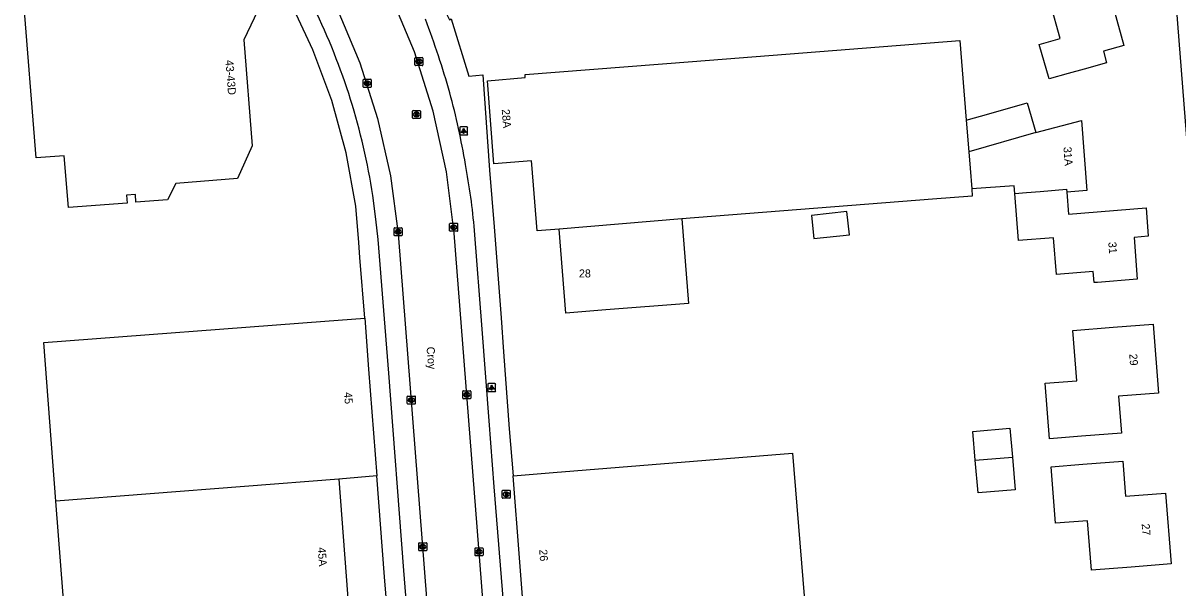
# Model space of a CAD drawing. Extents: x 157793 to 159380, y 380882 to 382313.
# Drawn here: x 158058.2 to 158202.5, y 381350.9 to 381421.5 of the extents above; entities that cross this region are included whole.
import ezdxf

# ---------------------------------------------------------------- set-up
doc = ezdxf.new("R2010")
doc.units = 0
for name, color, linetype in [('IMGEO_Brandkraan', 7, 'Continuous'), ('IMGEO_Kolk', 7, 'Continuous'), ('IMGEO_Lichtpunt', 7, 'Continuous'), ('IMGEO_Openbare_ruimte_label', 7, 'Continuous'), ('IMGEO_Pand', 7, 'Continuous'), ('IMGEO_Pand_nummerreeks', 7, 'Continuous'), ('IMGEO_Rijbaan_lokaal_gesloten', 7, 'Continuous'), ('IMGEO_Rioolput', 7, 'Continuous'), ('IMGEO_Voetpad_open', 7, 'Continuous')]:
    doc.layers.add(name, color=color, linetype=linetype)

msp = doc.modelspace()

# ---------------------------------------------------------------- linework, layer by layer
at = {"layer": 'IMGEO_Brandkraan'}
for p, q in [((158118.1, 381362.21), (158118.1, 381363.06)), ((158118.18, 381363.13), (158119.03, 381363.13)), ((158118.59, 381362.91), (158118.61, 381362.91)), ((158119.1, 381363.06), (158119.1, 381362.21)), ((158119.03, 381362.13), (158118.18, 381362.13)), ((158118.61, 381362.35), (158118.59, 381362.35))]:
    msp.add_line(p, q, dxfattribs=at)
for points in [[(158118.1, 381362.21), (158118.1, 381363.06)], [(158118.18, 381363.13), (158119.03, 381363.13)], [(158118.45, 381362.83), (158118.45, 381362.43), (158118.66, 381362.43)], [(158118.68, 381362.83), (158118.45, 381362.83)], [(158118.63, 381362.75), (158118.57, 381362.75), (158118.57, 381362.68)], [(158118.57, 381362.68), (158118.63, 381362.68)], [(158118.64, 381362.6), (158118.57, 381362.6), (158118.57, 381362.52)], [(158118.57, 381362.52), (158118.64, 381362.52)], [(158119.1, 381363.06), (158119.1, 381362.21)], [(158119.03, 381362.13), (158118.18, 381362.13)]]:
    msp.add_lwpolyline(points, dxfattribs=at)
for centre, radius, start, end in [((158118.18, 381363.06), 0.0765, 91.552, 178.448), ((158118.18, 381363.06), 0.0765, 91.552, 178.448), ((158118.63, 381362.71), 0.0379, 267.8285, 90.9355), ((158118.64, 381362.56), 0.0404, 269.8759, 90.5077), ((158118.67, 381362.68), 0.251, 268.6676, 293.5347), ((158118.68, 381362.69), 0.145, 59.4692, 91.5367), ((158118.71, 381362.73), 0.0922, 285.5137, 58.1501), ((158118.71, 381362.54), 0.105, 301.3115, 78.989), ((158119.03, 381363.06), 0.0765, 1.552, 88.448), ((158119.03, 381363.06), 0.0765, 1.552, 88.448), ((158118.18, 381362.21), 0.0765, 181.552, 268.448), ((158118.18, 381362.21), 0.0765, 181.552, 268.448), ((158119.03, 381362.21), 0.0765, 271.552, 358.448), ((158119.03, 381362.21), 0.0765, 271.552, 358.448)]:
    msp.add_arc(centre, radius, start, end, dxfattribs=at)
for centre, major_axis, ratio, start_param, end_param in [((158118.59, 381362.63), (-0.387, 0.002), 0.722429, 4.712389, 7.853982), ((158118.61, 381362.63), (-0.39, 0.002), 0.717154, 1.570796, 4.712389)]:
    msp.add_ellipse(centre, major_axis=major_axis, ratio=ratio, start_param=start_param, end_param=end_param, dxfattribs=at)
at = {"layer": 'IMGEO_Kolk'}
for p, q in [((158107.19, 381416.27), (158107.19, 381417.12)), ((158107.26, 381417.19), (158108.12, 381417.19)), ((158108.12, 381416.19), (158107.26, 381416.19)), ((158107.7, 381416.41), (158107.67, 381416.41)), ((158107.68, 381416.97), (158107.7, 381416.97)), ((158108.19, 381417.12), (158108.19, 381416.27)), ((158100.73, 381413.55), (158100.73, 381414.4)), ((158100.8, 381414.47), (158101.66, 381414.47)), ((158101.73, 381414.4), (158101.73, 381413.55)), ((158101.66, 381413.47), (158100.8, 381413.47)), ((158101.24, 381413.69), (158101.21, 381413.69)), ((158101.22, 381414.25), (158101.24, 381414.25)), ((158104.59, 381394.99), (158104.59, 381395.85)), ((158104.66, 381395.92), (158105.52, 381395.92)), ((158105.08, 381395.7), (158105.1, 381395.7)), ((158105.59, 381395.85), (158105.59, 381394.99)), ((158111.53, 381395.55), (158111.53, 381396.41)), ((158111.61, 381396.48), (158112.46, 381396.48)), ((158112.02, 381396.26), (158112.04, 381396.26)), ((158112.04, 381395.7), (158112.02, 381395.7)), ((158112.53, 381396.41), (158112.53, 381395.55)), ((158105.52, 381394.92), (158104.66, 381394.92)), ((158105.1, 381395.14), (158105.07, 381395.14)), ((158112.46, 381395.48), (158111.61, 381395.48)), ((158113.17, 381374.63), (158113.17, 381375.48)), ((158113.24, 381375.56), (158114.1, 381375.56)), ((158114.17, 381375.48), (158114.17, 381374.63)), ((158106.24, 381373.97), (158106.24, 381374.83)), ((158106.32, 381374.9), (158107.17, 381374.9)), ((158106.73, 381374.68), (158106.76, 381374.68)), ((158106.75, 381374.12), (158106.73, 381374.12)), ((158107.24, 381374.83), (158107.24, 381373.97)), ((158114.1, 381374.56), (158113.24, 381374.56)), ((158113.68, 381374.78), (158113.65, 381374.78)), ((158113.66, 381375.34), (158113.68, 381375.34)), ((158107.17, 381373.9), (158106.32, 381373.9)), ((158107.66, 381355.65), (158107.66, 381356.5)), ((158107.74, 381356.57), (158108.59, 381356.57)), ((158108.59, 381355.57), (158107.74, 381355.57)), ((158108.15, 381356.35), (158108.18, 381356.35)), ((158108.17, 381355.79), (158108.15, 381355.79)), ((158108.66, 381356.5), (158108.66, 381355.65)), ((158114.7, 381355.01), (158114.7, 381355.87)), ((158114.77, 381355.94), (158115.62, 381355.94)), ((158115.18, 381355.72), (158115.21, 381355.72)), ((158115.21, 381355.16), (158115.18, 381355.16)), ((158115.7, 381355.87), (158115.7, 381355.01)), ((158115.62, 381354.94), (158114.77, 381354.94))]:
    msp.add_line(p, q, dxfattribs=at)
for points in [[(158107.19, 381416.27), (158107.19, 381417.12)], [(158107.26, 381417.19), (158108.12, 381417.19)], [(158108.12, 381416.19), (158107.26, 381416.19)], [(158107.51, 381416.89), (158107.63, 381416.89), (158107.63, 381416.74), (158107.76, 381416.89), (158107.93, 381416.89), (158107.78, 381416.74), (158107.93, 381416.49), (158107.78, 381416.49), (158107.7, 381416.66), (158107.63, 381416.59), (158107.63, 381416.49), (158107.51, 381416.49), (158107.51, 381416.89)], [(158108.19, 381417.12), (158108.19, 381416.27)], [(158100.73, 381413.55), (158100.73, 381414.4)], [(158100.8, 381414.47), (158101.66, 381414.47)], [(158101.73, 381414.4), (158101.73, 381413.55)], [(158101.66, 381413.47), (158100.8, 381413.47)], [(158101.05, 381414.17), (158101.17, 381414.17), (158101.17, 381414.02), (158101.3, 381414.17), (158101.47, 381414.17), (158101.32, 381414.02), (158101.47, 381413.77), (158101.32, 381413.77), (158101.24, 381413.94), (158101.17, 381413.87), (158101.17, 381413.77), (158101.05, 381413.77), (158101.05, 381414.17)], [(158104.59, 381394.99), (158104.59, 381395.85)], [(158104.66, 381395.92), (158105.52, 381395.92)], [(158104.91, 381395.62), (158105.03, 381395.62), (158105.03, 381395.47), (158105.16, 381395.62), (158105.33, 381395.62), (158105.18, 381395.47), (158105.33, 381395.22), (158105.18, 381395.22), (158105.1, 381395.39), (158105.03, 381395.32), (158105.03, 381395.22), (158104.91, 381395.22), (158104.91, 381395.62)], [(158105.59, 381395.85), (158105.59, 381394.99)], [(158111.53, 381395.55), (158111.53, 381396.41)], [(158111.61, 381396.48), (158112.46, 381396.48)], [(158111.85, 381396.18), (158111.98, 381396.18), (158111.98, 381396.03), (158112.1, 381396.18), (158112.27, 381396.18), (158112.12, 381396.03), (158112.28, 381395.78), (158112.12, 381395.78), (158112.04, 381395.95), (158111.98, 381395.88), (158111.98, 381395.78), (158111.85, 381395.78), (158111.85, 381396.18)], [(158112.53, 381396.41), (158112.53, 381395.55)], [(158105.52, 381394.92), (158104.66, 381394.92)], [(158112.46, 381395.48), (158111.61, 381395.48)], [(158113.17, 381374.63), (158113.17, 381375.48)], [(158113.24, 381375.56), (158114.1, 381375.56)], [(158114.17, 381375.48), (158114.17, 381374.63)], [(158106.24, 381373.97), (158106.24, 381374.83)], [(158106.32, 381374.9), (158107.17, 381374.9)], [(158106.56, 381374.6), (158106.69, 381374.6), (158106.69, 381374.45), (158106.82, 381374.6), (158106.98, 381374.6), (158106.84, 381374.45), (158106.99, 381374.2), (158106.84, 381374.2), (158106.75, 381374.37), (158106.69, 381374.3), (158106.69, 381374.2), (158106.56, 381374.2), (158106.56, 381374.6)], [(158107.24, 381374.83), (158107.24, 381373.97)], [(158114.1, 381374.56), (158113.24, 381374.56)], [(158113.49, 381375.26), (158113.61, 381375.26), (158113.61, 381375.1), (158113.74, 381375.26), (158113.91, 381375.26), (158113.76, 381375.11), (158113.91, 381374.86), (158113.76, 381374.86), (158113.68, 381375.02), (158113.61, 381374.95), (158113.61, 381374.86), (158113.49, 381374.86), (158113.49, 381375.26)], [(158107.17, 381373.9), (158106.32, 381373.9)], [(158107.66, 381355.65), (158107.66, 381356.5)], [(158107.74, 381356.57), (158108.59, 381356.57)], [(158108.59, 381355.57), (158107.74, 381355.57)], [(158107.98, 381356.27), (158108.11, 381356.27), (158108.11, 381356.12), (158108.24, 381356.27), (158108.4, 381356.27), (158108.25, 381356.12), (158108.41, 381355.87), (158108.25, 381355.87), (158108.17, 381356.04), (158108.11, 381355.97), (158108.11, 381355.87), (158107.98, 381355.87), (158107.98, 381356.27)], [(158108.66, 381356.5), (158108.66, 381355.65)], [(158114.7, 381355.01), (158114.7, 381355.87)], [(158114.77, 381355.94), (158115.62, 381355.94)], [(158115.02, 381355.64), (158115.14, 381355.64), (158115.14, 381355.49), (158115.27, 381355.64), (158115.43, 381355.64), (158115.29, 381355.49), (158115.44, 381355.24), (158115.29, 381355.24), (158115.2, 381355.4), (158115.14, 381355.34), (158115.14, 381355.24), (158115.02, 381355.24), (158115.02, 381355.64)], [(158115.7, 381355.87), (158115.7, 381355.01)], [(158115.62, 381354.94), (158114.77, 381354.94)]]:
    msp.add_lwpolyline(points, dxfattribs=at)
for centre, start, end in [((158107.27, 381417.12), 91.552, 178.448), ((158107.27, 381417.12), 91.552, 178.448), ((158107.27, 381416.27), 181.552, 268.448), ((158107.27, 381416.27), 181.552, 268.448), ((158108.11, 381417.12), 1.552, 88.448), ((158108.11, 381417.12), 1.552, 88.448), ((158108.11, 381416.27), 271.552, 358.448), ((158108.11, 381416.27), 271.552, 358.448), ((158100.8, 381414.4), 91.552, 178.448), ((158100.8, 381414.4), 91.552, 178.448), ((158101.65, 381414.4), 1.552, 88.448), ((158101.65, 381414.4), 1.552, 88.448), ((158100.8, 381413.55), 181.552, 268.448), ((158100.8, 381413.55), 181.552, 268.448), ((158101.65, 381413.55), 271.552, 358.448), ((158101.65, 381413.55), 271.552, 358.448), ((158104.66, 381395.85), 91.552, 178.448), ((158104.66, 381395.85), 91.552, 178.448), ((158105.51, 381395.85), 1.552, 88.448), ((158105.51, 381395.85), 1.552, 88.448), ((158111.61, 381396.41), 91.552, 178.448), ((158111.61, 381396.41), 91.552, 178.448), ((158112.46, 381396.41), 1.552, 88.448), ((158112.46, 381396.41), 1.552, 88.448), ((158104.66, 381395), 181.552, 268.448), ((158104.66, 381395), 181.552, 268.448), ((158105.51, 381395), 271.552, 358.448), ((158105.51, 381395), 271.552, 358.448), ((158111.61, 381395.56), 181.552, 268.448), ((158111.61, 381395.56), 181.552, 268.448), ((158112.46, 381395.56), 271.552, 358.448), ((158112.46, 381395.56), 271.552, 358.448), ((158113.25, 381375.48), 91.552, 178.448), ((158113.25, 381375.48), 91.552, 178.448), ((158114.09, 381375.48), 1.552, 88.448), ((158114.09, 381375.48), 1.552, 88.448), ((158106.32, 381374.83), 91.552, 178.448), ((158106.32, 381374.83), 91.552, 178.448), ((158106.32, 381373.98), 181.552, 268.448), ((158106.32, 381373.98), 181.552, 268.448), ((158107.17, 381374.83), 1.552, 88.448), ((158107.17, 381374.83), 1.552, 88.448), ((158107.17, 381373.98), 271.552, 358.448), ((158107.17, 381373.98), 271.552, 358.448), ((158113.25, 381374.63), 181.552, 268.448), ((158113.25, 381374.63), 181.552, 268.448), ((158114.09, 381374.63), 271.552, 358.448), ((158114.09, 381374.63), 271.552, 358.448), ((158107.74, 381356.5), 91.552, 178.448), ((158107.74, 381356.5), 91.552, 178.448), ((158107.74, 381355.65), 181.552, 268.448), ((158107.74, 381355.65), 181.552, 268.448), ((158108.59, 381356.5), 1.552, 88.448), ((158108.59, 381356.5), 1.552, 88.448), ((158108.59, 381355.65), 271.552, 358.448), ((158108.59, 381355.65), 271.552, 358.448), ((158114.77, 381355.86), 91.552, 178.448), ((158114.77, 381355.86), 91.552, 178.448), ((158115.62, 381355.86), 1.552, 88.448), ((158115.62, 381355.86), 1.552, 88.448), ((158114.77, 381355.02), 181.552, 268.448), ((158114.77, 381355.02), 181.552, 268.448), ((158115.62, 381355.02), 271.552, 358.448), ((158115.62, 381355.02), 271.552, 358.448)]:
    msp.add_arc(centre, 0.0765, start, end, dxfattribs=at)
for centre, major_axis, ratio, start_param, end_param in [((158107.68, 381416.69), (-0.387, 0.002), 0.722429, 4.712389, 7.853982), ((158107.7, 381416.69), (-0.39, 0.002), 0.717154, 1.570796, 4.712389), ((158101.22, 381413.97), (-0.387, 0.002), 0.722429, 4.712389, 7.853982), ((158101.24, 381413.97), (-0.39, 0.002), 0.717154, 1.570796, 4.712389), ((158105.08, 381395.42), (-0.387, 0.002), 0.722429, 4.712389, 7.853982), ((158105.1, 381395.42), (-0.39, 0.002), 0.717154, 1.570796, 4.712389), ((158112.02, 381395.98), (-0.387, 0.002), 0.722429, 4.712389, 7.853982), ((158112.04, 381395.98), (-0.39, 0.002), 0.717154, 1.570796, 4.712389), ((158106.73, 381374.4), (-0.387, 0.002), 0.722429, 4.712389, 7.853982), ((158106.75, 381374.4), (-0.39, 0.002), 0.717154, 1.570796, 4.712389), ((158113.66, 381375.06), (-0.387, 0.002), 0.722429, 4.712389, 7.853982), ((158113.68, 381375.06), (-0.39, 0.002), 0.717154, 1.570796, 4.712389), ((158108.15, 381356.07), (-0.387, 0.002), 0.722429, 4.712389, 7.853982), ((158108.17, 381356.07), (-0.39, 0.002), 0.717154, 1.570796, 4.712389), ((158115.18, 381355.44), (-0.387, 0.002), 0.722429, 4.712389, 7.853982), ((158115.21, 381355.44), (-0.39, 0.002), 0.717154, 1.570796, 4.712389)]:
    msp.add_ellipse(centre, major_axis=major_axis, ratio=ratio, start_param=start_param, end_param=end_param, dxfattribs=at)
at = {"layer": 'IMGEO_Lichtpunt'}
for p, q in [((158112.79, 381408.42), (158112.79, 381407.62)), ((158112.79, 381408.42), (158112.79, 381407.62)), ((158113.69, 381408.52), (158112.88, 381408.52)), ((158113.69, 381408.52), (158112.88, 381408.52)), ((158112.88, 381407.52), (158113.69, 381407.52)), ((158112.88, 381407.52), (158113.69, 381407.52)), ((158113.78, 381407.62), (158113.78, 381408.42)), ((158113.78, 381407.62), (158113.78, 381408.42)), ((158116.29, 381376.35), (158116.29, 381375.55)), ((158116.29, 381376.35), (158116.29, 381375.55)), ((158117.19, 381376.45), (158116.38, 381376.45)), ((158117.19, 381376.45), (158116.38, 381376.45)), ((158116.38, 381375.45), (158117.19, 381375.45)), ((158116.38, 381375.45), (158117.19, 381375.45)), ((158117.28, 381375.55), (158117.28, 381376.35)), ((158117.28, 381375.55), (158117.28, 381376.35))]:
    msp.add_line(p, q, dxfattribs=at)
for points in [[(158113.16, 381408.09), (158113.2, 381408.06), (158113.01, 381407.8), (158112.97, 381407.83), (158113.16, 381408.09)], [(158113.26, 381408.04), (158113.31, 381408.04), (158113.31, 381407.72), (158113.26, 381407.72), (158113.26, 381408.04)], [(158113.37, 381408.06), (158113.41, 381408.09), (158113.6, 381407.82), (158113.56, 381407.8), (158113.37, 381408.06)], [(158116.66, 381376.02), (158116.7, 381375.99), (158116.51, 381375.73), (158116.47, 381375.76), (158116.66, 381376.02)], [(158116.76, 381375.97), (158116.81, 381375.97), (158116.81, 381375.65), (158116.76, 381375.65), (158116.76, 381375.97)], [(158116.87, 381375.99), (158116.91, 381376.02), (158117.1, 381375.75), (158117.06, 381375.73), (158116.87, 381375.99)]]:
    msp.add_lwpolyline(points, dxfattribs=at)
for centre in [(158113.29, 381408.22), (158116.79, 381376.15)]:
    msp.add_circle(centre, 0.0994, dxfattribs=at)
for centre, start, end in [((158112.88, 381408.42), 90, 180), ((158112.88, 381408.42), 90, 180), ((158112.88, 381407.62), 180, 270), ((158112.88, 381407.62), 180, 270), ((158113.69, 381408.42), 0, 90), ((158113.69, 381408.42), 0, 90), ((158113.69, 381407.62), 270, 0), ((158113.69, 381407.62), 270, 360), ((158116.38, 381376.35), 90, 180), ((158116.38, 381376.35), 90, 180), ((158116.38, 381375.55), 180, 270), ((158116.38, 381375.55), 180, 270), ((158117.19, 381376.35), 0, 90), ((158117.19, 381376.35), 0, 90), ((158117.19, 381375.55), 270, 0), ((158117.19, 381375.55), 270, 360)]:
    msp.add_arc(centre, 0.0946, start, end, dxfattribs=at)
at = {"layer": 'IMGEO_Pand'}
for points in [[(158190.23, 381435.75), (158190.87, 381435.93), (158192.2, 381431.16), (158192.04, 381431.12), (158192.72, 381428.75), (158194.74, 381429.31), (158196.36, 381423.53), (158194.59, 381423.05), (158195.79, 381418.71), (158193.24, 381417.99), (158193.64, 381416.52), (158190.82, 381415.73), (158188.83, 381415.18), (158186.44, 381414.52), (158185.23, 381418.83), (158187.83, 381419.56), (158186.61, 381423.91), (158184, 381423.18), (158182.8, 381427.45), (158176.17, 381425.54), (158174.53, 381431.23), (158176.89, 381431.91), (158176.86, 381432)], [(158077.5, 381426.61), (158089.67, 381427.58), (158085.81, 381419.41), (158086.86, 381406.18), (158085.02, 381402.08), (158077.3, 381401.47), (158076.25, 381399.42), (158072.32, 381399.11), (158072.26, 381400.08), (158071.15, 381400.01), (158071.23, 381399.01), (158063.88, 381398.45), (158063.35, 381404.92), (158059.84, 381404.67), (158058.22, 381425.09)], [(158125.21, 381395.77), (158122.47, 381395.53), (158121.82, 381403.83), (158121.78, 381404.27), (158117.06, 381403.91), (158116.26, 381414.3), (158120.97, 381414.68), (158120.95, 381415.08), (158141.9, 381416.71), (158175.3, 381419.31), (158176.09, 381409.38)], [(158176.09, 381409.38), (158178.92, 381410.17), (158183.7, 381411.52), (158184.79, 381407.81)], [(158176.09, 381409.38), (158176.41, 381405.43)], [(158184.79, 381407.81), (158190.49, 381409.33), (158191.17, 381400.58), (158188.65, 381400.38)], [(158184.79, 381407.81), (158176.41, 381405.43)], [(158176.41, 381405.43), (158176.57, 381403.38), (158176.78, 381400.81)], [(158176.78, 381400.81), (158176.85, 381399.89), (158171.86, 381399.51), (158140.56, 381397.03)], [(158182.15, 381400.2), (158182.07, 381401.15), (158176.78, 381400.81)], [(158182.15, 381400.2), (158183.64, 381400.32), (158185.32, 381400.46), (158188.62, 381400.73), (158188.65, 381400.38)], [(158188.65, 381400.38), (158188.86, 381397.64), (158198.58, 381398.4), (158198.84, 381394.89), (158197.1, 381394.73), (158197.47, 381389.51), (158192.49, 381389.1), (158192.09, 381389.07), (158191.97, 381390.47), (158187.39, 381390.09), (158187.01, 381394.67), (158182.63, 381394.32), (158182.15, 381400.2)], [(158140.56, 381397.03), (158141.4, 381386.48), (158131.05, 381385.66), (158126.06, 381385.26), (158125.21, 381395.77)], [(158140.56, 381397.03), (158125.21, 381395.77)], [(158161.18, 381397.94), (158156.76, 381397.47), (158157.06, 381394.58), (158161.49, 381395.05), (158161.18, 381397.94)], [(158062.33, 381361.77), (158060.82, 381381.58), (158095.93, 381384.26), (158100.91, 381384.65)], [(158100.91, 381384.65), (158101.4, 381378.24), (158102.42, 381364.93)], [(158185.95, 381376.5), (158189.92, 381376.82), (158189.42, 381383.1), (158194.47, 381383.5), (158199.45, 381383.89), (158200.13, 381375.28), (158195.14, 381374.88), (158195.5, 381370.28), (158190.52, 381369.89), (158186.5, 381369.57), (158185.95, 381376.5)], [(158177.23, 381366.89), (158176.93, 381370.49), (158181.56, 381370.87), (158181.86, 381367.25)], [(158119.48, 381364.94), (158124.46, 381365.34), (158154.39, 381367.78), (158156.05, 381347.42)], [(158181.86, 381367.25), (158182.2, 381363.2), (158177.57, 381362.81), (158177.23, 381366.89)], [(158177.23, 381366.89), (158181.86, 381367.25)], [(158190.68, 381366.38), (158195.67, 381366.77), (158196.02, 381362.38), (158201, 381362.77), (158201.7, 381353.93), (158196.72, 381353.54), (158191.74, 381353.15), (158191.25, 381359.33), (158187.27, 381359.02), (158186.72, 381366.07), (158190.68, 381366.38)], [(158097.66, 381364.51), (158062.33, 381361.77)], [(158102.42, 381364.93), (158097.66, 381364.51)], [(158097.66, 381364.51), (158099.15, 381345.23)], [(158121.05, 381344.44), (158119.48, 381364.94)], [(158063.8, 381342.49), (158062.33, 381361.77)]]:
    msp.add_lwpolyline(points, dxfattribs=at)
at = {"layer": 'IMGEO_Rijbaan_lokaal_gesloten'}
for points in [[(158116.63, 381344.81), (158116.02, 381346.74), (158115.71, 381348.98), (158112.09, 381395.23), (158111.12, 381402.92), (158109.46, 381410.5), (158107.13, 381417.89), (158104.15, 381425.05), (158103.4, 381426.61), (158089.73, 381454.68), (158068.55, 381497.11)], [(158063.32, 381491.96), (158084.36, 381449.77), (158097, 381424.25), (158097.47, 381423.28), (158100.31, 381416.54), (158102.53, 381409.57), (158104.13, 381402.42), (158105.08, 381395.17), (158108.68, 381349.09), (158108.99, 381346.37), (158109.55, 381343.68), (158109.89, 381342.45), (158111.07, 381338.31), (158112.62, 381334.31), (158114.52, 381330.45), (158114.85, 381329.87), (158129.63, 381306.83), (158130.69, 381305.06), (158133.89, 381298.95)]]:
    msp.add_lwpolyline(points, dxfattribs=at)
at = {"layer": 'IMGEO_Rioolput'}
for p, q in [((158106.88, 381409.65), (158106.88, 381410.51)), ((158106.96, 381410.58), (158107.81, 381410.58)), ((158107.37, 381410.36), (158107.4, 381410.36)), ((158107.88, 381410.51), (158107.88, 381409.65)), ((158107.81, 381409.58), (158106.96, 381409.58)), ((158107.39, 381409.8), (158107.37, 381409.8))]:
    msp.add_line(p, q, dxfattribs=at)
for points in [[(158106.88, 381409.65), (158106.88, 381410.51)], [(158106.96, 381410.58), (158107.81, 381410.58)], [(158107.47, 381410.28), (158107.22, 381410.28), (158107.22, 381409.88)], [(158107.22, 381409.88), (158107.34, 381409.88), (158107.34, 381410.04), (158107.36, 381410.04)], [(158107.4, 381410.2), (158107.34, 381410.2), (158107.34, 381410.12)], [(158107.34, 381410.12), (158107.4, 381410.12)], [(158107.4, 381410.01), (158107.47, 381409.88), (158107.61, 381409.88), (158107.55, 381410.01)], [(158107.88, 381410.51), (158107.88, 381409.65)], [(158107.81, 381409.58), (158106.96, 381409.58)]]:
    msp.add_lwpolyline(points, dxfattribs=at)
for centre, radius, start, end in [((158106.96, 381410.5), 0.0765, 91.552, 178.448), ((158106.96, 381410.5), 0.0765, 91.552, 178.448), ((158107.35, 381409.99), 0.0533, 26.0293, 88.6989), ((158107.4, 381410.1), 0.0964, 77.0061, 93.1865), ((158107.38, 381410.31), 0.19, 274.7715, 282.9687), ((158107.42, 381410.16), 0.0378, 276.6634, 79.6772), ((158107.47, 381410.17), 0.109, 350.3612, 89.416), ((158107.47, 381410.17), 0.112, 277.5842, 350.9817), ((158107.45, 381409.95), 0.108, 29.5134, 73.7905), ((158107.81, 381410.5), 0.0765, 1.552, 88.448), ((158107.81, 381410.5), 0.0765, 1.552, 88.448), ((158106.96, 381409.66), 0.0765, 181.552, 268.448), ((158106.96, 381409.66), 0.0765, 181.552, 268.448), ((158107.81, 381409.66), 0.0765, 271.552, 358.448), ((158107.81, 381409.66), 0.0765, 271.552, 358.448)]:
    msp.add_arc(centre, radius, start, end, dxfattribs=at)
for centre, major_axis, ratio, start_param, end_param in [((158107.37, 381410.08), (-0.387, 0.002), 0.722429, 4.712389, 7.853982), ((158107.39, 381410.08), (-0.39, 0.002), 0.717154, 1.570796, 4.712389)]:
    msp.add_ellipse(centre, major_axis=major_axis, ratio=ratio, start_param=start_param, end_param=end_param, dxfattribs=at)
at = {"layer": 'IMGEO_Voetpad_open'}
for points in [[(158100.91, 381384.65), (158100.31, 381392.19), (158100.16, 381394.1), (158099.8, 381398.61), (158098.59, 381405.28), (158096.8, 381411.81), (158094.42, 381418.15), (158092.35, 381422.61), (158086.43, 381434.52), (158083.68, 381440.17), (158072.05, 381463.05)], [(158107.95, 381429.04), (158108.92, 381427.09), (158111.52, 381421.91), (158111.72, 381422.01), (158113.91, 381414.88), (158115.68, 381415.03), (158116.51, 381403.11), (158117.08, 381396.04), (158117.95, 381384.66), (158118.26, 381380.41), (158118.97, 381370.8), (158119.48, 381364.94)], [(158200.59, 381322.78), (158204.14, 381323.05), (158210.22, 381323.52), (158205.2, 381387.52), (158201.92, 381429.43)], [(158106.25, 381347.39), (158105.81, 381353.11), (158103.92, 381377.78), (158102.6, 381394.48), (158102.31, 381397.02), (158101.93, 381399.96)], [(158116.88, 381345.56), (158118.2, 381347.52), (158118.31, 381347.81), (158118.33, 381348.11), (158117.09, 381363.57), (158116.45, 381371.8), (158115.61, 381383.27), (158114.64, 381395.6)], [(158103.82, 381346.79), (158103.71, 381348.29), (158103.39, 381352.3), (158102.42, 381364.93)]]:
    msp.add_lwpolyline(points, dxfattribs=at)
for centre, radius, start, end in [((158020.96, 381387.46), 81.93, 8.775, 26.0144), ((158013.08, 381385.12), 102.28, 15.6976, 21.1161), ((158022.39, 381388.51), 92.4, 9.5535, 15.2354), ((158032.36, 381388.45), 82.59, 4.969, 10.7461)]:
    msp.add_arc(centre, radius, start, end, dxfattribs=at)

# ---------------------------------------------------------------- texts
at = {"layer": 'IMGEO_Openbare_ruimte_label'}
msp.add_text('Croy', height=1, rotation=274.4163, dxfattribs=at).set_placement((158108.64, 381381.03))
at = {"layer": 'IMGEO_Pand_nummerreeks'}
for s, rotation, p in [('43-43D', 274.5319, (158083.5, 381416.85)), ('28A', 274.4116, (158118.04, 381410.71)), ('31A', 274.3829, (158188.24, 381406)), ('31', 274.1251, (158193.85, 381394.13)), ('29', 274.5213, (158196.46, 381380.15)), ('45', 274.3747, (158098.33, 381375.36)), ('27', 274.5172, (158198.02, 381358.92)), ('45A', 274.4321, (158095.03, 381355.97)), ('26', 274.3835, (158122.72, 381355.71))]:
    msp.add_text(s, height=1, rotation=rotation, dxfattribs=at).set_placement(p)
msp.add_text('28', height=1, dxfattribs=at).set_placement((158127.69, 381389.72))

doc.saveas('drawing.dxf')
